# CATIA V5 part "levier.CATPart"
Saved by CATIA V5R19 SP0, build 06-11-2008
Part number: skl_levier
Publications: "Plan.1", "axe_pivot_levier_batit", "axe_pivot_levier_bielette1"
Bounding box of the stored display mesh (mm): x -150 to 0, y 560 to 580, z -20 to 20
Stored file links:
  C:\Users\Thibaud\Desktop\IFMA\thinkmotion\IAO\modele_catia\squelette\levier.CATPart
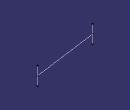
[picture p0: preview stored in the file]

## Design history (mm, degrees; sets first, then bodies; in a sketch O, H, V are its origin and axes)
Body1 (main body)
  Point1 "Point.12": stored without definition
  Point2 "Point.3": stored without definition
  Line1: type PtPt, SecondPoint Point2, FirstPoint Point1
  Plane1: stored without definition
  Point3 "Point.12": stored without definition
  Line2 "axe_pivot_levier_batit": type Normal, RefSkin Plane1, Start -20, End 20, RefPoint Point3
  Plane2: stored without definition
  Point4 "Point.3": stored without definition
  Line3 "axe_pivot_levier_bielette1": type Normal, RefSkin Plane2, Start -20, End 20, RefPoint Point4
